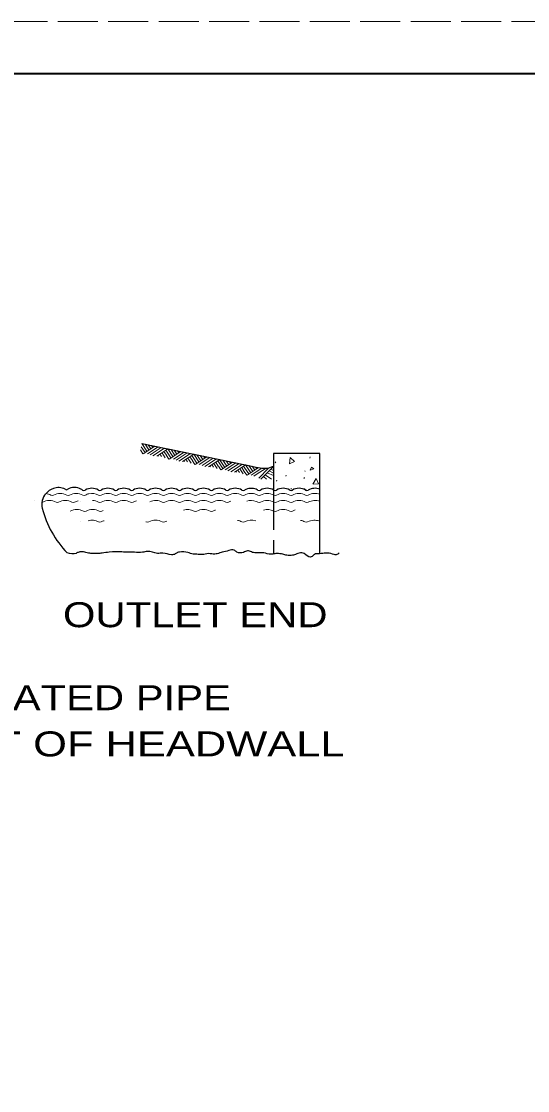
# Model space of a CAD drawing. Extents: x 1083.1 to 1117.1, y 697.4 to 743.4.
# Drawn here: x 1099.45 to 1104.31, y 709.08 to 719.35 of the extents above; entities that cross this region are included whole.
import ezdxf

# ---------------------------------------------------------------- set-up
doc = ezdxf.new("R2010")
doc.units = 0
doc.header["$LTSCALE"] = 0.064
doc.linetypes.add('LONG_DASHED', pattern=[7.5, 6, -1.5])
doc.layers.add('1', color=7, linetype='Continuous', lineweight=13)

msp = doc.modelspace()

# ---------------------------------------------------------------- linework, layer by layer
at = {"layer": '1', "lineweight": 25}
for p, q in [((1100.60867, 715.29908), (1100.85783, 715.24767)), ((1100.85767, 715.24767), (1101.10683, 715.19625)), ((1101.10675, 715.19617), (1101.35608, 715.14475)), ((1101.87183, 715.20375), (1101.87175, 714.85425)), ((1102.31742, 715.20375), (1101.87183, 715.20375)), ((1102.31733, 714.24083), (1102.31742, 715.20375)), ((1101.35592, 715.14475), (1101.60517, 715.09325)), ((1101.605, 715.09325), (1101.70767, 715.072)), ((1102.04033, 714.86525), (1102.04475, 714.85858))]:
    msp.add_line(p, q, dxfattribs=at)
at = {"layer": '1'}
for p, q in [((1100.658, 715.224), (1100.60867, 715.29908)), ((1100.67683, 715.23642), (1100.63975, 715.29275)), ((1100.6955, 715.24875), (1100.67083, 715.28633)), ((1100.61942, 715.20083), (1100.59625, 715.23617)), ((1100.63917, 715.21167), (1100.60267, 715.26733)), ((1100.73317, 715.2735), (1100.62283, 715.20083)), ((1100.76433, 715.267), (1100.66208, 715.19983)), ((1100.79558, 715.26058), (1100.68825, 715.19)), ((1100.71442, 715.26108), (1100.702, 715.27992)), ((1100.82667, 715.25417), (1100.71558, 715.18108)), ((1100.85783, 715.24767), (1100.75142, 715.17783)), ((1100.76967, 715.17708), (1100.76383, 715.18592)), ((1100.79892, 715.1735), (1100.78267, 715.19833)), ((1100.83417, 715.16083), (1100.80142, 715.21058)), ((1100.84483, 715.18533), (1100.82017, 715.223)), ((1100.85142, 715.21658), (1100.839, 715.23542)), ((1100.86858, 715.14933), (1100.84542, 715.18467)), ((1100.88825, 715.16017), (1100.85183, 715.21583)), ((1100.90717, 715.1725), (1100.85767, 715.24767)), ((1100.98233, 715.222), (1100.87192, 715.14925)), ((1100.92592, 715.18483), (1100.88883, 715.24133)), ((1101.0135, 715.2155), (1100.91117, 715.14833)), ((1100.94467, 715.19725), (1100.92, 715.23483)), ((1101.04458, 715.20908), (1100.93733, 715.1385)), ((1100.96358, 715.20958), (1100.95117, 715.22833)), ((1101.07575, 715.20267), (1100.96467, 715.12967)), ((1101.10683, 715.19625), (1101.00058, 715.12642)), ((1101.1005, 715.165), (1101.08808, 715.18375)), ((1101.15633, 715.121), (1101.10675, 715.19617)), ((1101.175, 715.13342), (1101.138, 715.18967)), ((1101.19383, 715.14567), (1101.16917, 715.18325)), ((1101.01883, 715.12567), (1101.013, 715.13442)), ((1101.04808, 715.12208), (1101.03175, 715.14667)), ((1101.08325, 715.10942), (1101.05042, 715.15917)), ((1101.094, 715.13383), (1101.06925, 715.1715)), ((1101.11767, 715.09792), (1101.09442, 715.13317)), ((1101.1375, 715.10875), (1101.10092, 715.16433)), ((1101.23142, 715.17042), (1101.121, 715.09783)), ((1101.26258, 715.164), (1101.16033, 715.09692)), ((1101.29367, 715.15758), (1101.1865, 715.087)), ((1101.21275, 715.15808), (1101.20033, 715.17683)), ((1101.32492, 715.15117), (1101.21383, 715.07817)), ((1101.35608, 715.14475), (1101.24975, 715.07483)), ((1101.26783, 715.07408), (1101.26208, 715.083)), ((1101.29717, 715.07058), (1101.28083, 715.09525)), ((1101.33242, 715.05792), (1101.29967, 715.10767)), ((1101.34308, 715.08242), (1101.31842, 715.12008)), ((1101.34967, 715.11358), (1101.33725, 715.13233)), ((1101.36683, 715.04642), (1101.34358, 715.08167)), ((1101.38667, 715.05725), (1101.35008, 715.11292)), ((1101.40542, 715.0695), (1101.35592, 715.14475)), ((1101.4805, 715.119), (1101.37008, 715.04642)), ((1101.42408, 715.08192), (1101.38708, 715.13825)), ((1101.51175, 715.11258), (1101.40942, 715.04542)), ((1101.443, 715.09425), (1101.41817, 715.13192)), ((1101.54283, 715.10617), (1101.43558, 715.0355)), ((1101.46183, 715.10667), (1101.44933, 715.1255)), ((1101.57408, 715.09967), (1101.46292, 715.02658)), ((1101.60517, 715.09325), (1101.49875, 715.02333)), ((1101.59867, 715.06208), (1101.58633, 715.08083)), ((1101.6545, 715.01808), (1101.605, 715.09325)), ((1101.67333, 715.03042), (1101.63617, 715.08683)), ((1101.69208, 715.04275), (1101.66733, 715.08042)), ((1101.8905, 715.11367), (1101.895, 715.12367)), ((1102.22167, 715.15917), (1102.22608, 715.16917)), ((1101.51692, 715.02267), (1101.51125, 715.0315)), ((1101.54633, 715.019), (1101.53, 715.04383)), ((1101.5815, 715.00633), (1101.54883, 715.05617)), ((1101.59217, 715.03092), (1101.5675, 715.06842)), ((1101.61592, 714.995), (1101.59267, 715.03017)), ((1101.63575, 715.00575), (1101.59917, 715.06125)), ((1101.826, 715.06317), (1101.73183, 714.96633)), ((1101.87183, 715.078), (1101.7525, 714.95525)), ((1101.80442, 714.95533), (1101.77783, 714.98142)), ((1101.85308, 714.95533), (1101.7935, 714.99733)), ((1101.87183, 714.99025), (1101.81325, 715.01783)), ((1101.87183, 715.01508), (1101.82992, 715.03483)), ((1101.87183, 715.04), (1101.8465, 715.052)), ((1101.9915, 714.985), (1101.99592, 714.995)), ((1102.17292, 715.03492), (1102.17742, 715.02825)), ((1101.90167, 714.93633), (1101.90608, 714.94633)), ((1102.16458, 714.96183), (1102.169, 714.97183))]:
    msp.add_line(p, q, dxfattribs=at)
at = {"layer": '1', "linetype": 'LONG_DASHED', "lineweight": 25}
msp.add_line((1101.87183, 714.85325), (1101.87175, 714.23775), dxfattribs=at)
at = {"layer": '1', "linetype": 'LONG_DASHED'}
msp.add_lwpolyline([(1083.12642, 697.35408), (1117.12642, 697.35408), (1117.12642, 719.35408), (1083.12642, 719.35408)], close=True, dxfattribs=at)
at = {"layer": '1', "lineweight": 25}
msp.add_lwpolyline([(1085.12642, 718.85408), (1116.62642, 718.85408), (1116.62642, 697.85408), (1085.12642, 697.85408)], close=True, dxfattribs=at)
at = {"layer": '1', "lineweight": 40}
msp.add_lwpolyline([(1085.12642, 718.85408), (1116.62642, 718.85408), (1116.62642, 697.85408), (1085.12642, 697.85408)], close=True, dxfattribs=at)
msp.add_lwpolyline([(1085.12642, 718.85408), (1116.62642, 718.85408), (1116.62642, 697.85408), (1085.12642, 697.85408)], close=True, dxfattribs=at)
at = {"layer": '1'}
for points in [[(1102.0255, 715.10225), (1102.03433, 715.16558), (1102.07408, 715.12458), (1102.0265, 715.10258)], [(1101.72967, 715.0675), (1101.70767, 715.05308), (1101.61917, 714.995)], [(1101.76083, 715.06108), (1101.70775, 715.02608), (1101.65867, 714.99383)], [(1101.80208, 715.06125), (1101.70775, 714.99917), (1101.68475, 714.98408)], [(1101.71092, 715.05508), (1101.70775, 715.06), (1101.69858, 715.07392)], [(1102.25158, 714.90633), (1102.28158, 714.96292), (1102.30483, 714.91083), (1102.25275, 714.90633)]]:
    msp.add_lwpolyline(points, dxfattribs=at)
at = {"layer": '1', "lineweight": 25}
for points in [[(1101.70767, 715.072), (1101.76275, 715.06058), (1101.82133, 715.0615), (1101.85417, 715.07325), (1101.87183, 715.07958)], [(1102.166, 714.85567), (1102.17008, 714.86417), (1102.1875, 714.85125)]]:
    msp.add_lwpolyline(points, dxfattribs=at)
at = {"layer": '1'}
msp.add_lwpolyline([(1102.22383, 715.04267), (1102.23717, 715.07042), (1102.25942, 715.05375)], close=True, dxfattribs=at)
at = {"layer": '1', "lineweight": 25}
for centre, major_axis, start_param, end_param in [((1099.80735, 714.74534), (-0.13004, 0), 4.19883845, 5.09292908), ((1099.96036, 714.74534), (-0.13004, 0), 4.19883845, 5.22593946), ((1099.79596, 714.71633), (-0.14894, 0), 5.54608976, 6.5554381), ((1099.80978, 714.71204), (-0.16221, 0), 5.030561, 5.58378126), ((1099.88385, 714.87903), (-0.02402, 0), 1.01768059, 2.12391206), ((1099.97569, 714.73792), (0.13004, 0), 1.05724585, 1.18835101), ((1100.05219, 714.87162), (0.02402, 0), 4.15927324, 5.26550472), ((1100.1287, 714.73792), (0.13004, 0), 1.05724585, 2.08434685), ((1100.2052, 714.87162), (0.02402, 0), 4.15927324, 5.26550472), ((1100.28171, 714.73792), (0.13004, 0), 1.05724585, 2.08434685), ((1100.35821, 714.87162), (0.02402, 0), 4.15927324, 5.26550472), ((1100.43472, 714.73792), (0.13004, 0), 1.05724585, 2.08434685), ((1100.51123, 714.87162), (0.02402, 0), 4.15927324, 5.26550472), ((1100.58773, 714.73792), (0.13004, 0), 1.05724585, 2.08434685), ((1100.66424, 714.87162), (0.02402, 0), 4.15927324, 5.26550472), ((1100.74074, 714.73792), (0.13004, 0), 1.05724585, 2.08434685), ((1100.81725, 714.87162), (0.02402, 0), 4.15927324, 5.26550472), ((1100.89375, 714.73792), (0.13004, 0), 1.05724585, 2.08434685), ((1100.97026, 714.87162), (0.02402, 0), 4.15927324, 5.26550472), ((1101.04677, 714.73792), (0.13004, 0), 1.05724585, 2.08434685), ((1101.12327, 714.87162), (0.02402, 0), 4.15927324, 5.26550472), ((1101.19978, 714.73792), (0.13004, 0), 1.05724585, 2.08434685), ((1101.27628, 714.87162), (0.02402, 0), 4.15927324, 5.26550472), ((1101.35279, 714.73792), (0.13004, 0), 1.05724585, 2.08434685), ((1101.42929, 714.87162), (0.02402, 0), 4.15927324, 5.26550472), ((1101.5058, 714.73792), (0.13004, 0), 1.05724585, 2.08434685), ((1101.5823, 714.87162), (0.02402, 0), 4.15927324, 5.26550472), ((1101.65881, 714.73792), (0.13004, 0), 1.18534148, 2.08434685), ((1101.65881, 714.73792), (0.13004, 0), 1.05724585, 1.18534148), ((1101.73532, 714.87162), (0.02402, 0), 4.15927324, 5.26550472), ((1101.81182, 714.73792), (0.13004, 0), 1.05724585, 2.08434685), ((1101.88833, 714.87162), (0.02402, 0), 4.15927324, 5.26550472), ((1101.96483, 714.73792), (0.13004, 0), 1.05724585, 2.08434685), ((1102.04134, 714.87162), (0.02402, 0), 4.15927324, 5.26550472), ((1102.11784, 714.73792), (0.13004, 0), 1.05724585, 2.08434685), ((1102.11784, 714.73792), (0.13004, 0), 1.05724585, 2.08434685), ((1102.19435, 714.87162), (0.02402, 0), 4.15927324, 5.26550472), ((1102.27086, 714.73792), (0.13004, 0), 1.64773364, 2.08434685), ((1102.27086, 714.73792), (0.13004, 0), 1.20464748, 1.64773364), ((1100.55965, 714.90273), (-0.93499, 0), 0.24461371, 0.77495004)]:
    msp.add_ellipse(centre, major_axis=major_axis, ratio=0.999895, start_param=start_param, end_param=end_param, dxfattribs=at)
at = {"layer": '1'}
for centre, major_axis, start_param, end_param in [((1099.67125, 714.68945), (0.13004, 0), 1.52531072, 1.5253976), ((1099.67125, 714.68945), (0.13004, 0), 1.05724585, 1.44210317), ((1099.74775, 714.82314), (0.02402, 0), 4.15927324, 5.26550472), ((1099.82426, 714.68945), (0.13004, 0), 1.05724585, 2.08434685), ((1099.90076, 714.82314), (0.02402, 0), 4.15927324, 5.26550472), ((1099.97727, 714.68945), (0.13004, 0), 1.05724585, 2.08434685), ((1099.97569, 714.68912), (0.13004, 0), 1.18823489, 1.18835101), ((1100.05377, 714.82314), (0.02402, 0), 4.15927324, 5.26550472), ((1100.13028, 714.68945), (0.13004, 0), 1.80471214, 2.08434685), ((1100.1287, 714.68912), (0.13004, 0), 1.05724585, 1.7926157), ((1100.2052, 714.82281), (0.02402, 0), 4.15927324, 5.26550472), ((1100.28171, 714.68912), (0.13004, 0), 1.05724585, 2.08434685), ((1100.35821, 714.82281), (0.02402, 0), 4.15927324, 5.26550472), ((1100.43472, 714.68912), (0.13004, 0), 1.05724585, 2.08434685), ((1100.51123, 714.82281), (0.02402, 0), 4.15927324, 5.26550472), ((1100.58773, 714.68912), (0.13004, 0), 1.05724585, 2.08434685), ((1100.66424, 714.82281), (0.02402, 0), 4.15927324, 5.26550472), ((1100.74074, 714.68912), (0.13004, 0), 1.05724585, 2.08434685), ((1100.81725, 714.82281), (0.02402, 0), 4.15927324, 5.26550472), ((1100.89375, 714.68912), (0.13004, 0), 1.05724585, 2.08434685), ((1100.97026, 714.82281), (0.02402, 0), 4.15927324, 5.26550472), ((1101.04677, 714.68912), (0.13004, 0), 1.05724585, 2.08434685), ((1101.12327, 714.82281), (0.02402, 0), 4.15927324, 5.26550472), ((1101.19978, 714.68912), (0.13004, 0), 1.05724585, 2.08434685), ((1101.27628, 714.82281), (0.02402, 0), 4.15927324, 5.26550472), ((1101.35279, 714.68912), (0.13004, 0), 1.05724585, 2.08434685), ((1101.42929, 714.82281), (0.02402, 0), 4.15927324, 5.26550472), ((1101.5058, 714.68912), (0.13004, 0), 1.05724585, 2.08434685), ((1101.5823, 714.82281), (0.02402, 0), 4.15927324, 5.26550472), ((1101.65881, 714.68912), (0.13004, 0), 1.18534148, 2.08434685), ((1101.65881, 714.68912), (0.13004, 0), 1.05724585, 1.18534148), ((1101.73532, 714.82281), (0.02402, 0), 4.15927324, 5.26550472), ((1101.81182, 714.68912), (0.13004, 0), 1.05724585, 2.08434685), ((1101.88833, 714.82281), (0.02402, 0), 4.15927324, 5.26550472), ((1101.96483, 714.68912), (0.13004, 0), 1.05724585, 2.08434685), ((1102.04134, 714.82281), (0.02402, 0), 4.15927324, 5.26550472), ((1102.11784, 714.68912), (0.13004, 0), 1.05724585, 2.08434685), ((1102.19435, 714.82281), (0.02402, 0), 4.15927324, 5.26550472), ((1102.27086, 714.68912), (0.13004, 0), 1.64773364, 2.08434685), ((1102.27086, 714.68912), (0.13004, 0), 1.20464748, 1.64773364), ((1099.56746, 714.62141), (0.13004, 0), 1.52531072, 1.5253976), ((1099.64397, 714.7551), (0.02402, 0), 4.90060407, 5.26550472), ((1099.72047, 714.62141), (0.13004, 0), 1.05724585, 2.08434685), ((1099.79698, 714.7551), (0.02402, 0), 4.15927324, 5.26550472), ((1099.87348, 714.62141), (0.13004, 0), 1.05724585, 2.08434685), ((1099.98343, 714.53471), (0.13004, 0), 1.05724585, 2.07953842), ((1099.94999, 714.7551), (0.02402, 0), 4.15927324, 5.26550472), ((1100.0265, 714.62141), (0.13004, 0), 1.80471214, 2.08434685), ((1099.97569, 714.62141), (0.13004, 0), 1.18823489, 1.18835101), ((1100.13644, 714.53471), (0.13004, 0), 1.05724585, 2.08434685), ((1100.1287, 714.62141), (0.13004, 0), 1.05724585, 1.5253976), ((1100.2052, 714.7551), (0.02402, 0), 4.15927324, 5.26550472), ((1100.28171, 714.62141), (0.13004, 0), 1.05724585, 2.08434685), ((1100.35821, 714.7551), (0.02402, 0), 4.15927324, 5.26550472), ((1100.43472, 714.62141), (0.13004, 0), 1.05724585, 2.08434685), ((1100.51123, 714.7551), (0.02402, 0), 4.15927324, 5.26550472), ((1100.58773, 714.62141), (0.13004, 0), 1.80471214, 2.08434685), ((1100.74074, 714.62141), (0.13004, 0), 1.05724585, 2.00974445), ((1100.81725, 714.7551), (0.02402, 0), 4.15927324, 5.26550472), ((1100.89375, 714.62141), (0.13004, 0), 1.05724585, 2.08434685), ((1100.97026, 714.7551), (0.02402, 0), 4.15927324, 5.26550472), ((1101.04677, 714.62141), (0.13004, 0), 1.05724585, 2.08434685), ((1101.04677, 714.53471), (0.13004, 0), 1.05724585, 1.87986233), ((1101.12327, 714.7551), (0.02402, 0), 4.15927324, 5.26550472), ((1101.19978, 714.62141), (0.13004, 0), 1.05724585, 2.08434685), ((1101.19978, 714.53471), (0.13004, 0), 1.05724585, 2.08434685), ((1101.27628, 714.7551), (0.02402, 0), 4.15927324, 5.26550472), ((1101.35279, 714.62141), (0.13004, 0), 1.05724585, 2.08434685), ((1101.42929, 714.7551), (0.02402, 0), 4.15927324, 5.26550472), ((1101.5058, 714.62141), (0.13004, 0), 1.90591879, 2.08434685), ((1101.65881, 714.62141), (0.13004, 0), 1.18534148, 1.91021846), ((1101.65881, 714.62141), (0.13004, 0), 1.05724585, 1.18534148), ((1101.73532, 714.7551), (0.02402, 0), 4.15927324, 5.26550472), ((1101.81182, 714.62141), (0.13004, 0), 1.05724585, 2.08434685), ((1101.81182, 714.53471), (0.13004, 0), 1.05724585, 1.85395554), ((1101.88833, 714.7551), (0.02402, 0), 4.15927324, 5.26550472), ((1101.96483, 714.62141), (0.13004, 0), 1.05724585, 2.08434685), ((1101.96483, 714.53471), (0.13004, 0), 1.05724585, 2.08434685), ((1102.04134, 714.7551), (0.02402, 0), 4.15927324, 5.26550472), ((1102.11784, 714.62141), (0.13004, 0), 1.05724585, 2.08434685), ((1102.19435, 714.7551), (0.02402, 0), 4.15927324, 5.26550472), ((1102.27086, 714.62141), (0.13004, 0), 1.64773364, 2.08434685), ((1102.27086, 714.62141), (0.13004, 0), 1.20464748, 1.64773364), ((1099.97569, 714.53471), (0.13004, 0), 1.18823489, 1.18835101), ((1100.05994, 714.6684), (0.02402, 0), 4.15927324, 5.26550472), ((1100.1287, 714.43177), (0.13004, 0), 1.05724585, 1.85313868), ((1100.21295, 714.6684), (0.02402, 0), 4.15927324, 5.26550472), ((1100.28945, 714.53471), (0.13004, 0), 1.97936995, 2.08434685), ((1100.74074, 714.43177), (0.13004, 0), 1.05724585, 2.08434685), ((1101.12327, 714.6684), (0.02402, 0), 4.15927324, 5.26550472), ((1101.27628, 714.6684), (0.02402, 0), 4.15927324, 5.26550472), ((1101.35279, 714.53471), (0.13004, 0), 1.85920423, 2.08434685), ((1101.65881, 714.43177), (0.13004, 0), 1.23319516, 2.08434685), ((1101.88833, 714.6684), (0.02402, 0), 4.15927324, 5.26550472), ((1102.04134, 714.6684), (0.02402, 0), 4.15927324, 5.26550472), ((1102.11784, 714.53471), (0.13004, 0), 1.84763047, 2.08434685), ((1099.97569, 714.43177), (0.13004, 0), 1.18823489, 1.18835101), ((1100.2052, 714.56546), (0.02402, 0), 4.15927324, 5.26550472), ((1100.28171, 714.43177), (0.13004, 0), 1.84245993, 2.08434685), ((1100.58773, 714.43177), (0.13004, 0), 1.05724585, 1.09640071), ((1100.66424, 714.56546), (0.02402, 0), 4.15927324, 5.26550472), ((1100.81725, 714.56546), (0.02402, 0), 4.15927324, 5.26550472), ((1100.89375, 714.43177), (0.13004, 0), 1.91970267, 2.08434685), ((1101.5058, 714.43177), (0.13004, 0), 1.05724585, 1.40496033), ((1101.5823, 714.56546), (0.02402, 0), 4.15927324, 5.26550472), ((1102.11143, 714.43177), (0.13004, 0), 1.05724585, 1.40496033), ((1102.18794, 714.56546), (0.02402, 0), 4.15927324, 5.26550472), ((1102.26444, 714.43177), (0.13004, 0), 1.59834179, 2.08434685), ((1102.26444, 714.43177), (0.13004, 0), 1.23319516, 1.59834179)]:
    msp.add_ellipse(centre, major_axis=major_axis, ratio=0.999895, start_param=start_param, end_param=end_param, dxfattribs=at)
at = {"layer": '1', "lineweight": 25}
for points in [[(1100.08275, 714.24867), (1100.03783, 714.25767), (1100.01317, 714.25642), (1099.98475, 714.24733), (1099.97708, 714.24333), (1099.89167, 714.24858)], [(1101.70775, 714.24967), (1101.68, 714.24983), (1101.64175, 714.26425), (1101.622, 714.26667), (1101.58442, 714.25275), (1101.52067, 714.25542), (1101.496, 714.27433), (1101.44308, 714.27), (1101.38142, 714.25375), (1101.33325, 714.23983), (1101.3105, 714.23517), (1101.24833, 714.24033), (1101.188, 714.23117), (1101.15, 714.23367), (1101.10283, 714.23633), (1101.0495, 714.25083), (1100.9705, 714.25592), (1100.9525, 714.25133), (1100.93017, 714.23725), (1100.89242, 714.23025), (1100.81175, 714.24492), (1100.75867, 714.24292), (1100.66133, 714.26217), (1100.61458, 714.25308), (1100.53867, 714.2535), (1100.48117, 714.25375), (1100.41742, 714.2565), (1100.29475, 714.25467), (1100.22825, 714.24567), (1100.17992, 714.24108), (1100.13142, 714.24133), (1100.10867, 714.24392), (1100.08275, 714.24867)], [(1102.26092, 714.22825), (1102.22517, 714.20683), (1102.16808, 714.24017), (1102.1195, 714.24517), (1102.07308, 714.22892), (1102.055, 714.22425), (1102.00042, 714.22458), (1101.96217, 714.23408), (1101.906, 714.24158), (1101.88483, 714.23925), (1101.84708, 714.23483), (1101.78, 714.247), (1101.74508, 714.2495), (1101.70775, 714.24967)], [(1102.50442, 714.24783), (1102.47458, 714.22908), (1102.45492, 714.23158), (1102.39225, 714.24608), (1102.36058, 714.24392), (1102.2985, 714.23942), (1102.27583, 714.23725), (1102.26092, 714.22825)]]:
    msp.add_spline(points, degree=3, dxfattribs=at)

# ---------------------------------------------------------------- texts
at = {"layer": '1'}
for s, width, p in [('OUTLET END', 1.25, (1099.85108, 713.53375)), ('CORRUGATED PIPE', 1.25, (1097.58583, 712.73608)), ('END TREATMENT OF HEADWALL', 1.3, (1095.90267, 712.2925))]:
    msp.add_text(s, height=0.24, dxfattribs=dict(at, width=width)).set_placement(p)

doc.saveas('drawing.dxf')
